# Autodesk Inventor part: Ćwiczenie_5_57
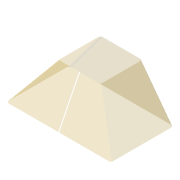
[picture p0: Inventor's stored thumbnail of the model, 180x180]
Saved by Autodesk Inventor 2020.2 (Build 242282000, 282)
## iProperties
Created: 2005-06
Part Number: Ćwiczenie_5_57
Document SubType Name: Modeling
Designer: F.Stasiak
Manufacturer: Standard
Standards Organization: Custom
Density: 1 g/cm^3
Material: Ogólny
Appearance: Domyślna
Manager: www.cadconsulting.pl
Company: Fabian Stasiak CAD Consulting
Author: F.Stasiak
Subject: Zbiór ćwiczeń. Autodesk Inventor 2020. Kurs podstawowy
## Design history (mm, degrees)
sketch "Szkic1"
  geometry: L1 (-125, 75)-(125, 75); L2 (125, 75)-(125, -75); L3 (-125, -75)-(-125, 75); L4 (0, 75)-(0, -75); L5 (-125, -75)-(-1, -75); L6 (125, -75)-(1, -75); 2 further points
  constraints: 12 end point, 2 equal length, 2 midpoint, 2 perpendicular, 2 point on line, 1 coincident, 1 horizontal, 1 parallel
  dimensions: "d1" = 250 distance of L1.start L1.end; "d2" = 150 distance of L3.start L1.start; "d3" = 1 distance of L5.end L4.end; "d4" = 1 distance of L4.end L6.end (= d3)
node "Płaszczyzna konstrukcyjna1"
sketch "Szkic2"
  geometry: L1 (-50, 75)-(50, 75); L2 (50, 75)-(50, -25); L3 (-50, -25)-(-50, 75); L4 (-125, 75)-(125, 75) reference; L5 (0, -25)-(0, 75); L6 (-50, -25)-(-1, -25); L7 (50, -25)-(1, -25); 1 further point
  constraints: 12 end point, 2 equal length, 2 perpendicular, 2 point on line, 1 collinear, 1 horizontal, 1 midpoint, 1 parallel
  dimensions: "d6" = 100 distance of L1.start L1.end; "d7" = 100 distance of L1.end L2.end; "d8" = 1 distance of L5.start L6.end (= d4); "d9" = 1 distance of L5.start L7.end (= d4)
feature "PowWyciągnięciaZłożonego1" sketch "Szkic2" dims "d10" = 0, "d11" = 90 deg, "d12" = 0, "d13" = 90 deg
fillet "Zaokrąglenie1" dims "d14" = 5
node "Korpusy bryłowe"
node "Korpusy powierzchniowe"
body "Srf1"
